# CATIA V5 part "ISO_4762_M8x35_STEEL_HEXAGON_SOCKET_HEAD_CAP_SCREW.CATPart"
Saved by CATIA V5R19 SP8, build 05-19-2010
Part number: ISO 4762 SCREW M8x35 STEEL HEXAGON SOCKET HEAD CAP
Nomenclature: 24
Publications: "Mating Face", "Axis"
Bounding box of the stored display mesh (mm): x -35 to 8, y -6.5 to 6.5, z -6.49 to 6.49
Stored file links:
  C:\Users\rphgr\Desktop\0_Tapis_TC520B_vitesse\ISO_4762_M8x35_STEEL_HEXAGON_SOCKET_HEAD_CAP_SCREW.CATPart
  D:\Programmes\DassaultSysteme\win_b64\startup\components\MechanicalStandardParts\EN_Standards\Design_Tables\EN_ISO_4762_HEXAGON_SOCKET_HEAD_CAP_SCREW.txt
  C:\Program Files\Dassault Systemes\B19\win_b64\startup\components\MechanicalStandardParts\ISO_Standards\Design_Tables\ISO_4762_HEXAGON_SOCKET_HEAD_CAP_SCREW.txt
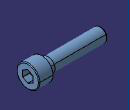
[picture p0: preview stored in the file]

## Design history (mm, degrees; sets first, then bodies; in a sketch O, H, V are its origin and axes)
Parameters
  d_dia = 8 mm
  l_nom = 35 mm
  k_head_depth_max = 8 mm
  s_nom = 6 mm
  r_min = 0.4 mm
  ds_max = 8 mm
  e = 6.863 mm
  t_min = 4 mm
  p_pitch = 1.25 mm
  Threading = 31.25 mm
  dk_max = 13 mm
Body1 "PartBody" (main body)
  Sketch1 on yz-plane, origin (0, 0, 0), H (0, 1, 0), V (0, 0, 1)
    circle A1 centre (0, 0) radius 6.5
    radius A1 = 6.5 {= dk_max /2}
  Pad1: profile Sketch1, direction (1, 0, 0), length 8 {= k_head_depth_max}
  Fillet1: radius 0.4 {= r_min}, on edge [face of Pad1 | face of Pad1]
  Body2
    Sketch2 on face of Pad1, origin (8, 0, 0), H (0, 1, 0), V (0, 0, 1)
      point P1 (3, -1.7321)
      point P2 (3, 1.7321)
      point P3 (0, 3.4641)
      point P4 (-3, 1.7321)
      point P5 (-3, -1.7321)
      point P6 (0, -3.4641)
      point P7 (3, 0)
      line L1 (3, -1.7321) -> (3, 1.7321)
      line L2 (3, 1.7321) -> (0, 3.4641)
      line L3 (0, 3.4641) -> (-3, 1.7321)
      line L4 (-3, 1.7321) -> (-3, -1.7321)
      line L5 (-3, -1.7321) -> (0, -3.4641)
      line L6 (0, -3.4641) -> (3, -1.7321)
      construction line L7 (0, 0) -> (3, 0)
      construction circle A1 centre (0, 0) radius 3.4641
      construction arc A2 centre (-3, -1.7321) radius 3.4641 from (-3, 1.7321) to (0, -3.4641) cw
      construction arc A3 centre (3, 1.7321) radius 3.4641 from (0, 3.4641) to (3, -1.7321) ccw
      point P8 (-3, -1.7321)
      point P9 (3, 1.7321)
      distance L1 L4 = 6 {= s_nom}
      horizontal: L7 H
      coincidence: A1 P1, A1 P2, A1 P3, A1 P4, A1 P5, A1 P6, A2 P4, A2 P6, A2 O, P8 P5, A3 P3, A3 P1, A3 O, P9 P2
      midpoint: P7 L1
    Pad2: profile Sketch2, direction (-1, 0, 0), length 5.9778 {= t_min +(e /3.47)}
    Body3
      Sketch3 on zx-plane, origin (0, 0, 0), H (-1, 0, 0), V (0, 0, 1)
        point P1 (-2.0188, 0)
        line L1 (-2.0188, 0) -> (-4, 3.4315)
        line L2 (-4, 3.4315) -> (-8, 3.4315)
        line L3 (-8, 3.4315) -> (-8, 0)
        axis line L4 (-46.2384, 0) -> (26.3409, 0)
        reference projected line E1 (-8, -6.9227) -> (-8, 6.9227) from edge [face of Pad2 | face of Pad2]
        length L2 = 4 {= t_min}
        angle L1 L4 = 60
        distance L2 L4 = 3.4315 {= e /2}
        horizontal: L2 H, L4 H
        perpendicularity: L3 L2
        fix: L4
        coincidence: L3 E1, P1 L4
      Shaft1: profile Sketch3, axis Sketch3.L4, angle 360
    Intersect1: tool Body3
  Remove1: tool Body2
  Sketch4 on xy-plane, origin (0, 0, 0), H (1, 0, 0), V (0, 1, 0)
    line L1 (0, 0) -> (0, 4)
    line L2 (0, 4) -> (-3.75, 4)
    line L3 (-3.75, 4) -> (-3.75, 3.9024)
    line L4 (-3.75, 3.9024) -> (-35, 3.9024)
    line L5 (-35, 3.9024) -> (-35, 0)
    axis line L6 (-192.3446, 0) -> (99.1594, 0)
    distance L5 L1 = 35 {= l_nom}
    distance L3 L5 = 31.25 {= Threading}
    distance L2 L6 = 4 {= ds_max /2}
    distance L4 L6 = 3.9024 {= d_dia /2.05}
    vertical: L1 V, L3 V, L5 V
    horizontal: L2 H, L4 H, L6 H
    fix: L6
  Shaft2: profile Sketch4, axis Sketch4.L6, angle 360
  Fillet2: radius 0.4 {= r_min}, on edge [face of Shaft2 | face of Pad1]
  Chamfer1: length 1.25 {= p_pitch}, angle 45, on edge [face of Shaft2 | face of Shaft2]
  Thread1: diameter 7.8049 {= d_dia /1.025}, depth 31.25 {= Threading}, pitch 1, on face of Shaft2, from face of Shaft2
